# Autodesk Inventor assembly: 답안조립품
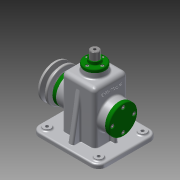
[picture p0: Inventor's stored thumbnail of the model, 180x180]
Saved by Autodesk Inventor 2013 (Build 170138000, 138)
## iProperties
Created: 2016-06
Part Number: 답안조립품
Document SubType Name: Assembly
Designer: k
Author: k
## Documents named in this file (19)
- C:\Users\k\Desktop\Manufacturing2급-강민정\답안조립품.iam
- C:\Users\k\Desktop\Manufacturing2급-강민정\본체.ipt
- C:\Users\k\Desktop\Manufacturing2급-강민정\공용부품\앞커버.ipt
- C:\Users\k\Desktop\Manufacturing2급-강민정\공용부품\뒤커버.ipt
- C:\Users\k\Desktop\Manufacturing2급-강민정\공용부품\상부부시.ipt
- C:\Users\k\Desktop\Manufacturing2급-강민정\공용부품\오일실 15 25 7.ipt
- C:\Users\k\Desktop\Manufacturing2급-강민정\공용부품\편심축.ipt
- C:\Users\k\Desktop\Manufacturing2급-강민정\공용부품\베어링 15 x 35 x 11.ipt
- C:\Users\k\Desktop\Manufacturing2급-강민정\공용부품\멈춤링 15 x 1.ipt
- C:\Users\k\Desktop\Manufacturing2급-강민정\공용부품\키 5 x 5 x 14.ipt
- C:\Users\k\Desktop\Manufacturing2급-강민정\공용부품\V-벨트풀리.ipt
- C:\Users\k\Desktop\Manufacturing2급-강민정\공용부품\와셔.ipt
- C:\Users\k\Desktop\Manufacturing2급-강민정\공용부품\볼트 M6 x 12.ipt
- C:\Users\k\Desktop\Manufacturing2급-강민정\공용부품\링크.ipt
- C:\Users\k\Desktop\Manufacturing2급-강민정\공용부품\슬라이드바.ipt
- C:\Users\k\Desktop\Manufacturing2급-강민정\공용부품\고정핀.ipt
- C:\Users\k\Desktop\Manufacturing2급-강민정\공용부품\멈춤링 6 x 5.ipt
- C:\Users\k\Desktop\Manufacturing2급-강민정\공용부품\볼트 M4 x 10.ipt
- C:\Users\k\Desktop\Manufacturing2급-강민정\공용부품\볼트 M3 x 8.ipt
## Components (15 placed, 5 different names)
1. V-벨트풀리:1 — 각도:2, 각도:4
2. ISO 4018 M6 x 12:1
3. 고정핀:1
4. ISO 4762 M4 x 10:1
5. ISO 4762 M4 x 10:2
6. ISO 4762 M4 x 10:3
7. ISO 4762 M4 x 10:4
8. ISO 4762 M4 x 10:5
9. ISO 4762 M4 x 10:6
10. ISO 4762 M4 x 10:7
11. ISO 4762 M4 x 10:8
12. ISO 4762 M3 x 8:1
13. ISO 4762 M3 x 8:2
14. ISO 4762 M3 x 8:3
15. ISO 4762 M3 x 8:4
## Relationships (2: Angle 2)
- 각도:2 [Angle]: V-벨트풀리:1
- 각도:4 [Angle]: V-벨트풀리:1
